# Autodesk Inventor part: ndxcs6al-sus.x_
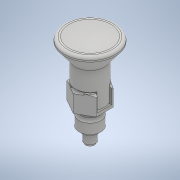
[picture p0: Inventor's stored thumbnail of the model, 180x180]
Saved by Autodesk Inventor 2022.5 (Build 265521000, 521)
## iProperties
Created: 2018-04
Part Number: ndxcs6al-sus.x_
Material: 一般
Document SubType Name: Modeling
Designer: imaocorp
Density: 1 g/cm^3
Appearance: 既定
Sending System: SOLIDWORKS 2016-2016286
MC: AMD64
MC_MODEL: AMD64 Family 21 Model 2 Stepping 0, AuthenticAMD
OS: Windows_NT
FRU: Parasolid Version 28.0, build 224,  7-29-2016
FORMAT: text
GUISE: transmit
KEY: ndxcs6al-sus
FILE: ndxcs6al-sus.x_t
DATE: Wed Apr 25 10:16:52 2018
Author: imaocorp
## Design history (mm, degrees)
feature "Base1"
node "ソリッド1"
